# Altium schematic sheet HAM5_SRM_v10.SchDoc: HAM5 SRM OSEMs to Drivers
size C; Engineer: L. Sanchez; Organization: LIGO Laboratory; Address1: California Institute of Technology; Address2: Massachusetts Institute of Technology; DocumentNumber: D1002740; Revision: v10; SheetNumber: 2; SheetTotal: 8
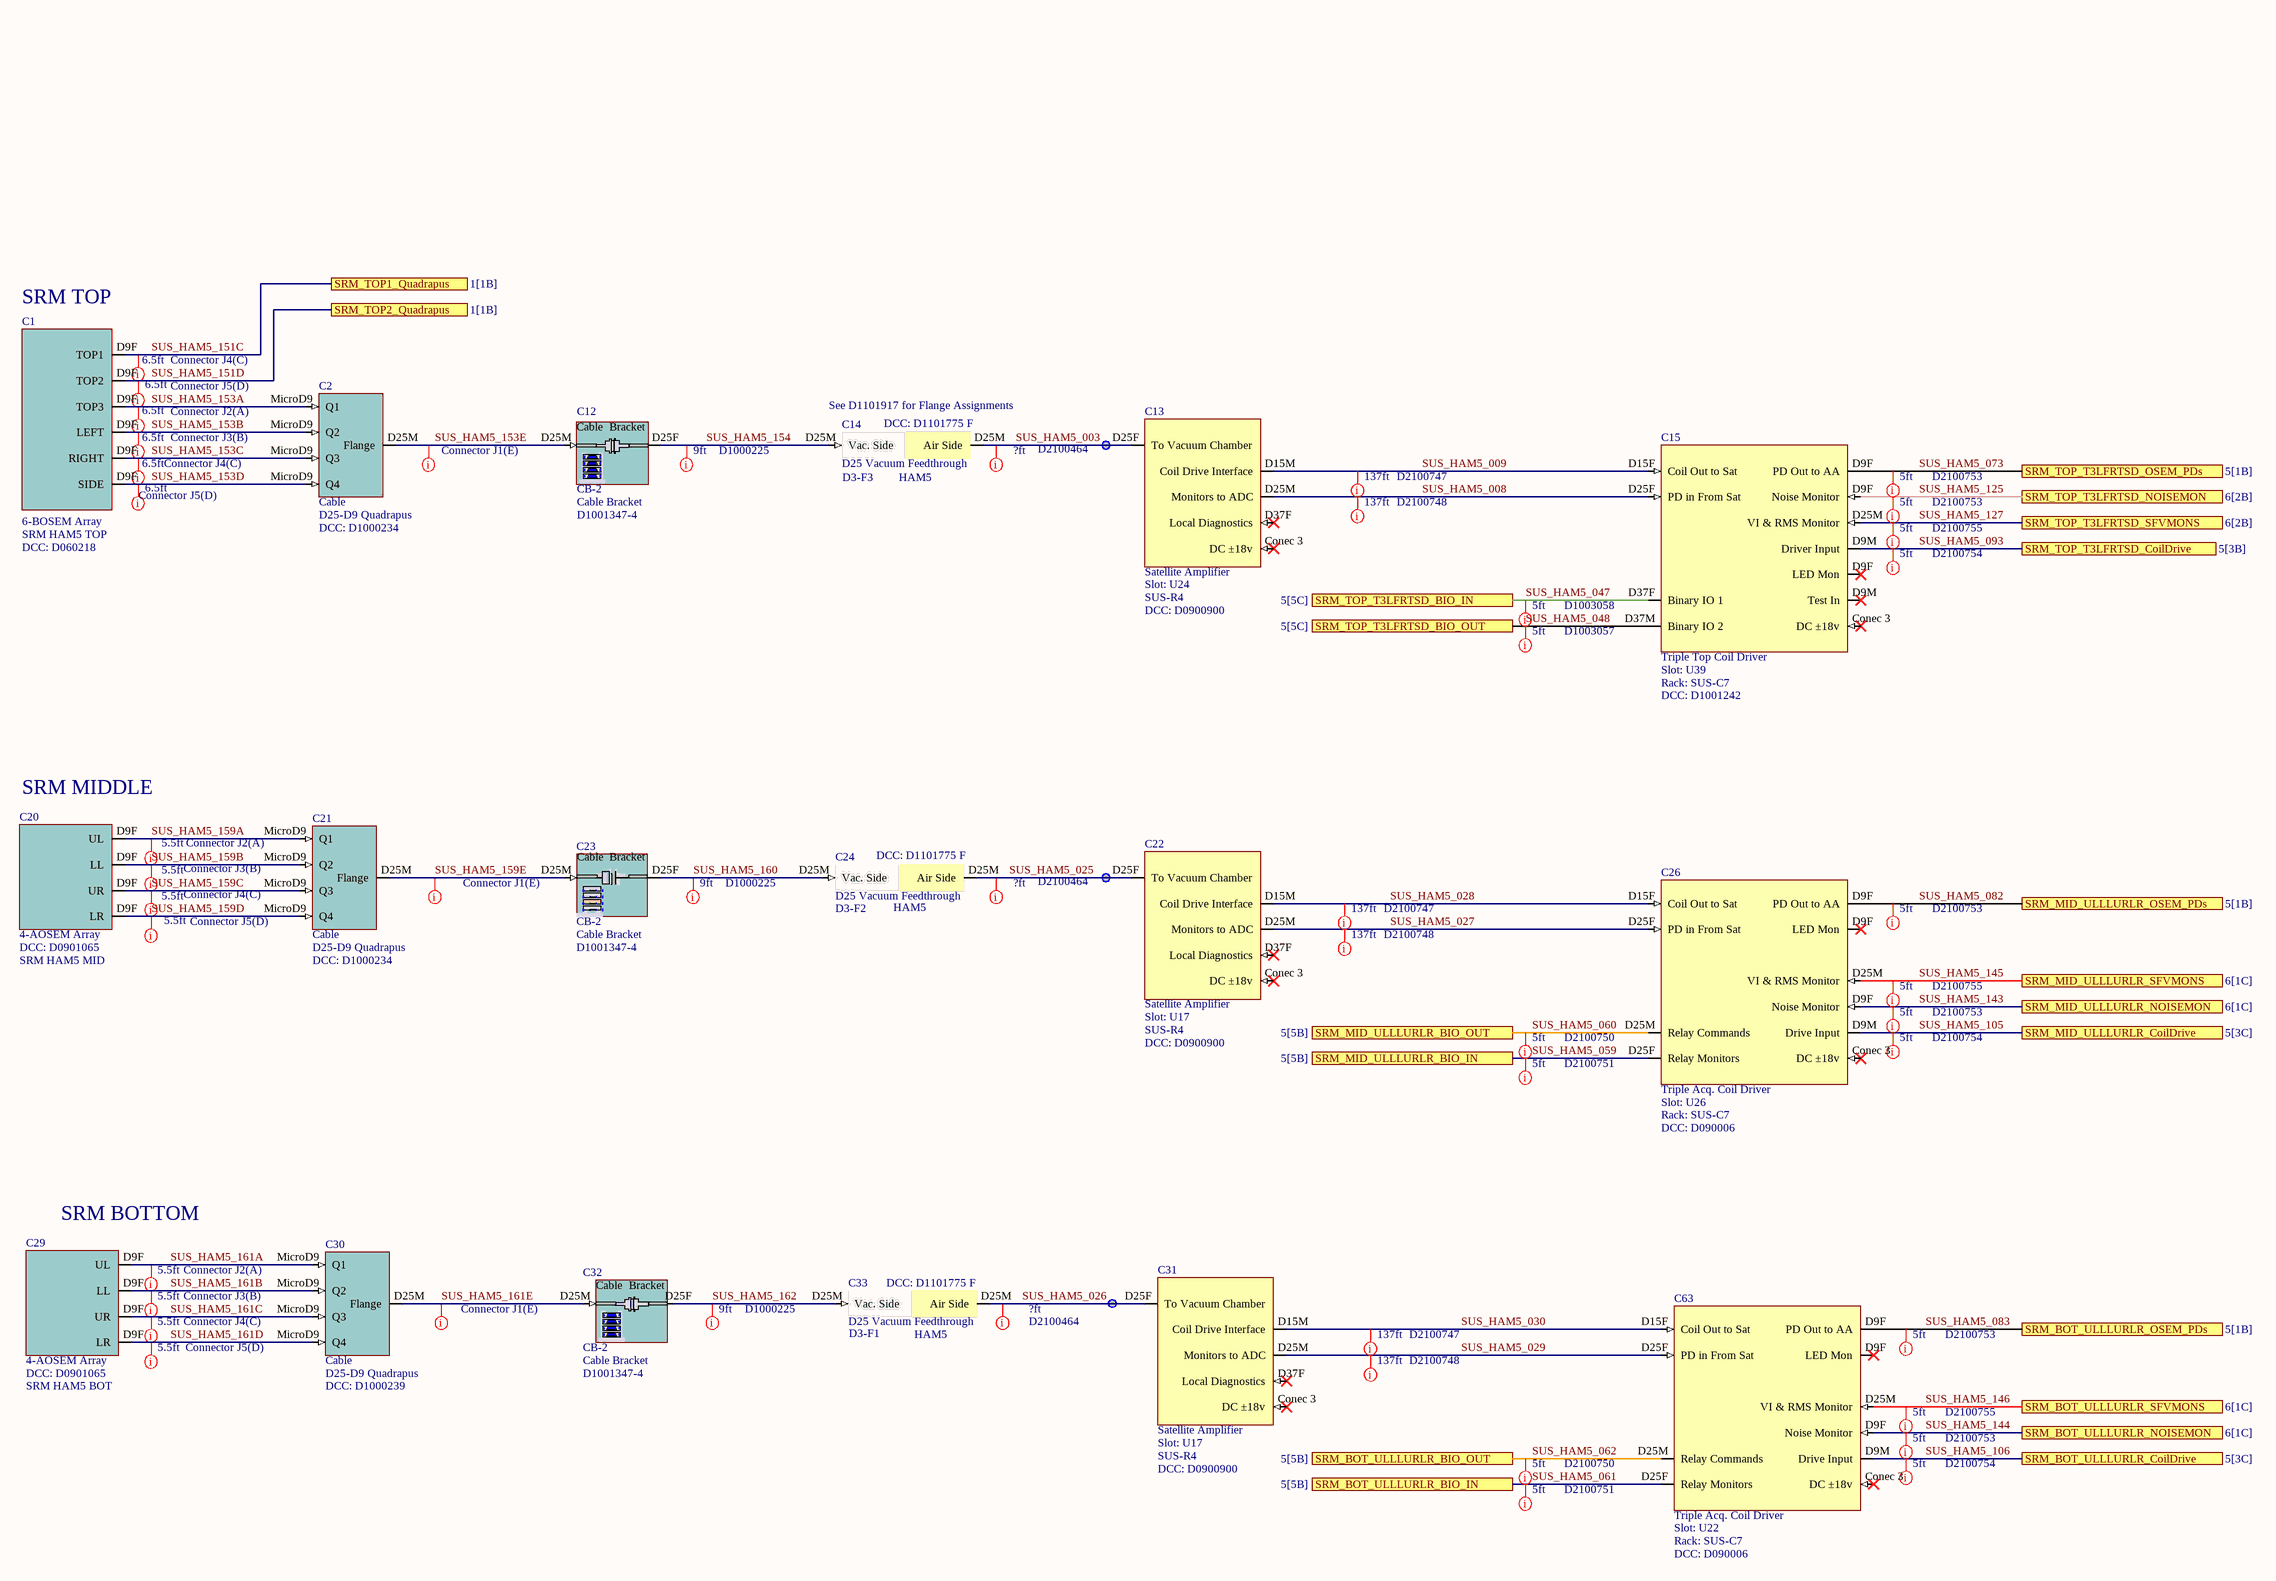
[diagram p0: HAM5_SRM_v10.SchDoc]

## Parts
C1  6-BOSEM Array  Parameter 1: SRM HAM5 TOP  DCC: D060218
C2  Cable  value D25-D9 Quadrapus  DCC: D1000234
C12  Slot: CB-2  DCC: D1001347-4  (hidden comment: Cable Bracket)
C13  Satellite Amplifier  Slot: U24  Rack: SUS-R4  DCC: D0900900
C14  D25 Vacuum Feedthrough  DCC: D1101775 F  Feedthrough: D3-F3  Chamber: HAM5
C15  Triple Top Coil Driver  Slot: U39  Rack: SUS-C7  DCC: D1001242
C20  4-AOSEM Array  DCC: D0901065  Parameter: SRM HAM5 MID
C21  Cable  value D25-D9 Quadrapus  DCC: D1000234
C22  Satellite Amplifier  Slot: U17  Rack: SUS-R4  DCC: D0900900
C23  Slot: CB-2  DCC: D1001347-4  (hidden comment: Cable Bracket)
C24  D25 Vacuum Feedthrough  DCC: D1101775 F  Feedthrough: D3-F2  Chamber: HAM5
C26  Triple Acq. Coil Driver  Slot: U26  Rack: SUS-C7  DCC: D090006
C29  4-AOSEM Array  DCC: D0901065  Parameter: SRM HAM5 BOT
C30  Cable  value D25-D9 Quadrapus  DCC: D1000239
C31  Satellite Amplifier  Slot: U17  Rack: SUS-R4  DCC: D0900900
C32  Slot: CB-2  DCC: D1001347-4  (hidden comment: Cable Bracket)
C33  D25 Vacuum Feedthrough  DCC: D1101775 F  Feedthrough: D3-F1  Chamber: HAM5
C63  Triple Acq. Coil Driver  Slot: U22  Rack: SUS-C7  DCC: D090006

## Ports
SRM_BOT_ULLLURLR_BIO_IN (see 5[5B]), SRM_BOT_ULLLURLR_BIO_OUT (see 5[5B]), SRM_BOT_ULLLURLR_CoilDrive (see 5[3C]), SRM_BOT_ULLLURLR_NOISEMON (see 6[1C]), SRM_BOT_ULLLURLR_OSEM_PDs (see 5[1B]), SRM_BOT_ULLLURLR_SFVMONS (see 6[1C]), SRM_MID_ULLLURLR_BIO_IN (see 5[5B]), SRM_MID_ULLLURLR_BIO_OUT (see 5[5B]), SRM_MID_ULLLURLR_CoilDrive (see 5[3C]), SRM_MID_ULLLURLR_NOISEMON (see 6[1C]), SRM_MID_ULLLURLR_OSEM_PDs (see 5[1B]), SRM_MID_ULLLURLR_SFVMONS (see 6[1C]), SRM_TOP1_Quadrapus (see 1[1B]), SRM_TOP2_Quadrapus (see 1[1B]), SRM_TOP_T3LFRTSD_BIO_IN (see 5[5C]), SRM_TOP_T3LFRTSD_BIO_OUT (see 5[5C]), SRM_TOP_T3LFRTSD_CoilDrive (see 5[3B]), SRM_TOP_T3LFRTSD_NOISEMON (see 6[2B]), SRM_TOP_T3LFRTSD_OSEM_PDs (see 5[1B]), SRM_TOP_T3LFRTSD_SFVMONS (see 6[2B])

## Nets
SUS_HAM5_003: C13.D25F(To_Vacuum_Chamber) C14.D25M(Air_Side)
SUS_HAM5_008: C13.D25M(Monitors_to_ADC) C15.D25F(PD_in_From_Sat)
SUS_HAM5_009: C13.D15M(Coil_Drive_Interface) C15.D15F(Coil_Out_to_Sat)
SUS_HAM5_025: C22.D25F(To_Vacuum_Chamber) C24.D25M(Air_Side)
SUS_HAM5_026: C31.D25F(To_Vacuum_Chamber) C33.D25M(Air_Side)
SUS_HAM5_027: C22.D25M(Monitors_to_ADC) C26.D25F(PD_in_From_Sat)
SUS_HAM5_028: C22.D15M(Coil_Drive_Interface) C26.D15F(Coil_Out_to_Sat)
SUS_HAM5_029: C31.D25M(Monitors_to_ADC) C63.D25F(PD_in_From_Sat)
SUS_HAM5_030: C31.D15M(Coil_Drive_Interface) C63.D15F(Coil_Out_to_Sat)
SUS_HAM5_047: C15.D37F(Binary_IO_1) ; port SRM_TOP_T3LFRTSD_BIO_IN
SUS_HAM5_048: C15.D37M(Binary_IO_2) ; port SRM_TOP_T3LFRTSD_BIO_OUT
SUS_HAM5_059: C26.D25F(Relay_Monitors) ; port SRM_MID_ULLLURLR_BIO_IN
SUS_HAM5_060: C26.D25M(Relay_Commands) ; port SRM_MID_ULLLURLR_BIO_OUT
SUS_HAM5_061: C63.D25F(Relay_Monitors) ; port SRM_BOT_ULLLURLR_BIO_IN
SUS_HAM5_062: C63.D25M(Relay_Commands) ; port SRM_BOT_ULLLURLR_BIO_OUT
SUS_HAM5_073: C15.D9F(PD_Out_to_AA) ; port SRM_TOP_T3LFRTSD_OSEM_PDs
SUS_HAM5_082: C26.D9F(PD_Out_to_AA) ; port SRM_MID_ULLLURLR_OSEM_PDs
SUS_HAM5_083: C63.D9F(PD_Out_to_AA) ; port SRM_BOT_ULLLURLR_OSEM_PDs
SUS_HAM5_093: C15.D9M(Test_In) ; port SRM_TOP_T3LFRTSD_CoilDrive
SUS_HAM5_105: C26.D9M(Drive_Input) ; port SRM_MID_ULLLURLR_CoilDrive
SUS_HAM5_106: C63.D9M(Drive_Input) ; port SRM_BOT_ULLLURLR_CoilDrive
SUS_HAM5_125: C15.D9F(Noise_Monitor) ; port SRM_TOP_T3LFRTSD_NOISEMON
SUS_HAM5_127: C15.D25M(VI_&_RMS_Monitor) ; port SRM_TOP_T3LFRTSD_SFVMONS
SUS_HAM5_143: C26.D9F(Noise_Monitor) ; port SRM_MID_ULLLURLR_NOISEMON
SUS_HAM5_144: C63.D9F(Noise_Monitor) ; port SRM_BOT_ULLLURLR_NOISEMON
SUS_HAM5_145: C26.D25M(VI_&_RMS_Monitor) ; port SRM_MID_ULLLURLR_SFVMONS
SUS_HAM5_146: C63.D25M(VI_&_RMS_Monitor) ; port SRM_BOT_ULLLURLR_SFVMONS
SUS_HAM5_151C: C1.D9F(TOP1) ; port SRM_TOP1_Quadrapus
SUS_HAM5_151D: C1.D9F(TOP2) ; port SRM_TOP2_Quadrapus
SUS_HAM5_153A: C1.D9F(TOP3) C2.MicroD9(Q1)
SUS_HAM5_153B: C1.D9F(LEFT) C2.MicroD9(Q2)
SUS_HAM5_153C: C1.D9F(RIGHT) C2.MicroD9(Q3)
SUS_HAM5_153D: C1.D9F(SIDE) C2.MicroD9(Q4)
SUS_HAM5_153E: C2.D25M(Flange) C12.D25M
SUS_HAM5_154: C12.D25F C14.D25M(Vac._Side)
SUS_HAM5_159A: C20.D9F(UL) C21.MicroD9(Q1)
SUS_HAM5_159B: C20.D9F(LL) C21.MicroD9(Q2)
SUS_HAM5_159C: C20.D9F(UR) C21.MicroD9(Q3)
SUS_HAM5_159D: C20.D9F(LR) C21.MicroD9(Q4)
SUS_HAM5_159E: C21.D25M(Flange) C23.D25M
SUS_HAM5_160: C23.D25F C24.D25M(Vac._Side)
SUS_HAM5_161A: C29.D9F(UL) C30.MicroD9(Q1)
SUS_HAM5_161B: C29.D9F(LL) C30.MicroD9(Q2)
SUS_HAM5_161C: C29.D9F(UR) C30.MicroD9(Q3)
SUS_HAM5_161D: C29.D9F(LR) C30.MicroD9(Q4)
SUS_HAM5_161E: C30.D25M(Flange) C32.D25M
SUS_HAM5_162: C32.D25F C33.D25M(Vac._Side)

Not connected (* = marked no-connect by the designer): C13 Conec 3(DC_±18v)* D37F(Local_Diagnostics)*; C15 Conec 3(DC_±18v)*; C22 Conec 3(DC_±18v)* D37F(Local_Diagnostics)*; C26 Conec 3(DC_±18v)*; C31 Conec 3(DC_±18v)* D37F(Local_Diagnostics)*; C63 Conec 3(DC_±18v)*

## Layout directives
Length: 5ft; DCC: Connector J1(E): SUS_HAM5_161E
Length: 5.5ft; DCC: Connector J1(E): SUS_HAM5_159E
Length: 6.5ft; DCC: Connector J1(E): SUS_HAM5_153E
Length: 6.5ft; DCC: Connector J2(A): SUS_HAM5_153A
Length: 6.5ft; DCC: Connector J3(B): SUS_HAM5_153B
Length: 6.5ft; DCC: Connector J4(C): SUS_HAM5_151C, SUS_HAM5_153C
Length: 6.5ft; DCC: Connector J5(D): SUS_HAM5_151D, SUS_HAM5_153D
Length: 5.5ft; DCC: Connector J2(A): SUS_HAM5_159A, SUS_HAM5_161A
Length: 5.5ft; DCC: Connector J3(B): SUS_HAM5_159B, SUS_HAM5_161B
Length: 5.5ft; DCC: Connector J4(C): SUS_HAM5_159C, SUS_HAM5_161C
Length: 5.5ft; DCC: Connector J5(D): SUS_HAM5_159D, SUS_HAM5_161D
Length: 9ft; DCC: D1000225: SUS_HAM5_154, SUS_HAM5_160, SUS_HAM5_162
Length: ?ft; DCC: D2100464: SUS_HAM5_003, SUS_HAM5_025, SUS_HAM5_026
Length: 137ft; DCC: D2100748: SUS_HAM5_008, SUS_HAM5_027, SUS_HAM5_029
Length: 137ft; DCC: D2100747: SUS_HAM5_009, SUS_HAM5_028, SUS_HAM5_030
Length: 5ft; DCC: D1003057: SUS_HAM5_048
Length: 5ft; DCC: D1003058: SUS_HAM5_047
Length: 5ft; DCC: D2100751: SUS_HAM5_059, SUS_HAM5_061
Length: 5ft; DCC: D2100750: SUS_HAM5_060, SUS_HAM5_062
Length: 5ft; DCC: D2100754: SUS_HAM5_093, SUS_HAM5_105, SUS_HAM5_106
Length: 5ft; DCC: D2100755: SUS_HAM5_127, SUS_HAM5_145, SUS_HAM5_146
Length: 5ft; DCC: D2100753: SUS_HAM5_073, SUS_HAM5_082, SUS_HAM5_083, SUS_HAM5_125, SUS_HAM5_143, SUS_HAM5_144

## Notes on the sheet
- (near C1) SRM TOP
- (near C14) See D1101917 for Flange Assignments
- (near C20) SRM MIDDLE
- (near C29) SRM BOTTOM

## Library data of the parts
C1 = 6-BOSEM Array HAM: Serial: Sxxxxxxx; System: SUS; Slot: U?; Rack: SUS-R?
C2 C21 C30 = Flange: Rack: SUS-R?; Serial: Sxxxxxxx; Slot: U?; System: SUS
C12 = Cable Bracket 3 1-4: Rack: SUS-R?; Serial: Sxxxxxxx; System: SUS
C13 C22 C31 = Satellite Amplifier: System: SUS; Serial: Sxxxxxxx
C14 C24 C33 = VacFeedD25: Serial: Sxxxxxxx; System: ISC; Rack: R?; Slot: U?
C15 = Triple Top CD: System: SUS; Serial: Sxxxxxxx
C20 C29 = 4-BOSEM Array: Rack: SUS-R?; Serial: Sxxxxxxx; Slot: U?; System: SUS
C23 = Cable Bracket 2 1-4: Rack: SUS-R?; Serial: Sxxxxxxx; System: SUS
C26 C63 = Triple Acquisition Coil Driver: System: SUS; Serial: Sxxxxxxx
C32 = Cable Bracket 1 1-4: Rack: SUS-R?; Serial: Sxxxxxxx; System: SUS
